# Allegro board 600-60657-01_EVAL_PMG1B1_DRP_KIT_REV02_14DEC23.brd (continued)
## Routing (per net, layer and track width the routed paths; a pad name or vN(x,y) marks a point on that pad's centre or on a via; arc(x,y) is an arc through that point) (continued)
C4: length 45.7
  TOP w0.381: v1(77.52,59.2) C89.2 C85.1 79.27,63.17 78.51,63.93 R86.1
  PWR/SIG w0.381: v1(77.52,59.2) 74.08,59.2 73.43,58.55 73.43,49.96 61.68,38.2 v1(61.68,31.2)
  BOTTOM w0.381: R79.1 v1(61.68,31.2)
CC1: length 91.9
  TOP w0.203: v3(75.97,47.36) 75.97,47.07 75.78,46.88 C22.1 75.29,46.45 75.44,46.3 76.27,46.3 76.66,45.91 77.46,45.91 78.01,45.36 U3.19 ; v2(104.31,4.91) 104.23,5 J10.A5
  PWR/SIG w0.305: v2(104.31,4.91) 104.88,4.91 105.18,5.22 105.18,5.92 104.88,6.22 104.47,6.22 103.7,6.99 98.48,6.99 74.85,30.62 74.85,42.28 76.97,44.4 76.97,46.36 v3(75.97,47.36)
  BOTTOM w0.305: D14.2 104.55,4.75 104.39,4.91 v2(104.31,4.91) ; v3(75.97,47.36) 75.49,47.36 74.92,46.79 55.16,46.79 54.78,47.17 J6.4
CC1_KP: length 2.2
  TOP w0.188: J1.A5 v1(7.35,38.49)
  BOTTOM w0.188: v1(7.35,38.49) 7.24,38.6 R70.2
CC2: length 92
  TOP w0.203: v2(104.59,6.84) 104.68,6.75 J10.B5 ; v3(77.43,47.33) 77.43,47.11 77.2,46.88 C25.1 76.74,46.44 76.89,46.29 77.7,46.29 78.41,45.58 U3.18
  PWR/SIG w0.305: v3(77.43,47.33) 77.43,44.21 75.31,42.09 75.31,30.82 98.67,7.45 103.98,7.45 v2(104.59,6.84)
  BOTTOM w0.305: v2(104.59,6.84) 104.61,6.82 104.62,6.82 104.69,6.75 J10.B5 ; v3(77.43,47.33) 77.43,46.67 77.08,46.31 52.62,46.31 52.24,46.7 J6.5
CC2_KP: length 2.2
  TOP w0.188: v1(7.3,35.49) J1.B5
  BOTTOM w0.188: R71.2 6.31,35.49 v1(7.3,35.49)
COMP: length 8
  TOP w0.188: U3.13 80.41,44.92 80.64,45.15 C38.1 84.21,46.02 84.3,46.11 84.3,46.97 R42.1
CSNO: length 37.1
  TOP w0.14: v5(79.42,48.3) 79.16,48.04 79.16,47.1 79.3,46.96 C27.2 79.81,46.47 79.16,45.82 79.16,43.34 79.21,43.28 U3.16 ; R49.1 98.21,61.96 97.73,61.48 97.73,60.88 v5(97.99,60.62)
  BOTTOM w0.14: v5(97.99,60.62) 97.74,60.37 97.74,58.59 95.91,56.76 81.14,56.76 80.54,56.15 80.54,50.48 79.17,49.12 79.17,48.54 v5(79.42,48.3)
CSPO: length 37.2
  TOP w0.14: R47.1 96.95,61.96 97.44,61.47 97.44,60.88 v5(97.18,60.62) ; U3.17 78.81,43.28 78.86,43.34 78.86,45.82 78.21,46.48 C27.1 78.72,46.96 78.86,47.1 78.86,48.04 v5(78.6,48.3)
  BOTTOM w0.14: v5(97.18,60.62) 97.45,60.35 97.45,58.71 95.79,57.05 81.02,57.05 80.25,56.28 80.25,50.61 78.88,49.24 78.88,48.57 v5(78.6,48.3)
DM_GPIO1: length 112.1
  TOP w0.14: v2(104.59,5.52) 104.82,5.75 J10.B7 ; v2(102.89,6.4) 103.14,6.16 103.46,6.16 103.58,6.29 J10.A7 ; U3.21 77.21,43.28 77.26,43.34 77.26,44.97 76.97,45.27 76.18,45.27 v2(75.93,45.03)
  PWR/SIG w0.114: v2(104.59,5.52) 103.78,5.52 v2(102.89,6.4) 102.65,6.16 97.92,6.16 74.17,29.91 74.17,44.25 75.19,45.27 75.69,45.27 v2(75.93,45.03)
  BOTTOM w0.14: J6.12 35.44,48.17 35.58,48.03 35.58,45.97 36.28,45.27 75.69,45.27 v2(75.93,45.03) ; DM_GPIO1.1 106.64,6.8 106.13,6.29 104.18,6.29 103.98,6.5 J10.A7 102.99,6.5 v2(102.89,6.4)
DP_GPIO0: length 112.6
  TOP w0.14: v2(75.93,45.81) 76.18,45.56 77.09,45.56 77.56,45.09 77.56,43.34 77.61,43.28 U3.20 ; v2(102.89,5.62) 103.14,5.87 103.44,5.87 103.58,5.73 J10.A6 103.97,5.5 104.72,6.25 J10.B6
  PWR/SIG w0.114: v2(102.89,5.62) 102.65,5.87 97.8,5.87 73.88,29.78 73.88,44.37 75.07,45.56 75.69,45.56 v2(75.93,45.81)
  BOTTOM w0.14: J6.11 36.01,48.17 35.87,48.03 35.87,46.09 36.4,45.56 75.69,45.56 v2(75.93,45.81) ; v2(102.89,5.62) 103.02,5.5 J10.A6 103.58,5.87 103.71,6 106.15,6 106.66,5.49 DP_GPIO0.1
HG1: length 15.8
  TOP w0.203: U3.2 81.88,37.97 v3(82.44,37.41)
  TOP w0.254: v2(93.33,36.94) 93.31,36.91 93.31,36.5 93.41,36.4 Q8.4 93.8,36.4 94.05,36.65 v2(94.05,36.94)
  TOP w0.406: v3(82.44,37.41) v3(82.86,36.99)
  PWR/SIG w0.406: v3(82.44,37.41) v3(82.86,36.99) 83.27,36.57 89.31,36.57 89.67,36.94 v2(93.33,36.94) 94.05,36.94 v2(94.05,36.94)
HG2: length 18.6
  TOP w0.203: U3.10 82.05,41.17 v3(82.55,41.67)
  TOP w0.254: v2(94.03,45.28) 94.03,44.85 93.84,44.66 Q7.4 93.56,44.66 93.38,44.84 v2(93.38,45.29)
  TOP w0.406: v3(82.55,41.67) 82.95,42.07 v3(83,42.07)
  PWR/SIG w0.406: v2(94.03,45.28) 94.03,45.29 v2(93.38,45.29) 93.02,45.65 84.1,45.65 83,44.55 v3(83,42.07) 82.61,41.67 v3(82.55,41.67)
I2C0_SCL: length 45.1
  TOP w0.188: U3.42 78.01,33.51 75.56,31.06 75.56,30.17 75.42,30.03 R35.1 R31.2 73.44,29.45 v2(73.19,29.19)
  BOTTOM w0.188: v2(73.19,29.19) 73.19,30.5 73.04,30.65 71.84,30.65 70.52,31.98 48.61,31.98 47.67,31.04 47.67,27.34 J7.6
I2C0_SDA: length 43.4
  TOP w0.188: U3.41 77.61,33.67 75.42,31.47 R34.1 73.49,31.47 R30.2 73.44,32.12 v2(73.19,32.37)
  BOTTOM w0.188: v2(73.19,32.37) 73.19,31.19 73.01,31.01 72.07,31.01 70.72,32.36 48.22,32.36 47.16,31.3 J7.7
I2C_SCL: length 90.1
  TOP w0.188: R31.1 70.68,30.03 70.47,30.24 v2(70.47,31.07) ; U1.38 14.13,32.05 14.05,31.96 R4.1 14.6,30.58 14.76,30.42 14.76,28.94 v5(15.2,28.5)
  PWR/SIG w0.15: v2(70.47,31.07) 69.12,31.07 68.22,30.17 55.14,30.17 54.93,30.38 54.93,42.15 54.33,42.76 43.29,42.76 38.8,38.27 35.65,38.27 J4.4 33.8,40.12 v1(33.03,40.12) 33.03,39.53 32.88,39.38 31.29,39.38 31.09,39.57 v1(31.09,40.14) 30.68,40.55 28.11,40.55 J3.4
  BOTTOM w0.188: v5(15.2,28.5) 15.36,28.34 23.81,28.34 24.78,29.32 24.78,38.93 25.22,39.37 J3.4
I2C_SDA: length 88.1
  TOP w0.188: U1.39 14.53,31.43 v5(14.63,31.33) ; v2(70.94,30.54) 70.94,31.31 71.15,31.52 R30.1
  PWR/SIG w0.15: J3.6 28.12,38.03 30.77,38.03 v1(31.1,37.7) 31.1,37.15 31.25,37 32.8,37 32.96,37.15 v1(32.96,37.71) 33.66,37.71 J4.6 35.66,37.94 38.97,37.94 43.47,42.45 54.08,42.45 54.62,41.91 54.62,30.21 54.97,29.86 68.41,29.86 69.09,30.54 v2(70.94,30.54)
  BOTTOM w0.188: R63.1 14.05,31.13 14.26,31.33 v5(14.63,31.33) 14.63,28.32 14.95,28 24.07,28 25.27,29.19 25.27,35.17 J3.6
IIN_CSN: length 13.5
  TOP w0.14: SP1.2 88.42,29.51 88.37,29.47 87.45,29.47 86.98,29.94 86.98,32.79 85.36,34.4 81.95,34.4 80.36,36 80.36,36.2 80.41,36.25 U3.48
IIN_CSP: length 14
  TOP w0.14: U3.47 80.01,36.25 80.06,36.2 80.06,35.88 81.83,34.11 85.24,34.11 86.69,32.67 86.69,29.82 87.33,29.18 88.38,29.18 88.42,29.13 SP2.2
IOUT_CSN: length 1.1
  TOP w0.14: SP4.1 97.77,63.83 98.2,63.41 R49.2
IOUT_CSP: length 1
  TOP w0.14: R47.2 96.95,63.41 97.39,63.85 SP3.1
KP3_UART_RX: length 61.8
  TOP w0.188: v5(24.4,42.29) 23.82,41.71 23.82,40.86 26.05,38.63 26.05,38.62 26.07,38.61 26.07,37.71 25.73,37.38 25.73,35.48 J3.8 ; v1(53.19,41.22) 54.87,39.55 R26.1 ; U1.21 11.32,38.72 v5(11.1,38.94)
  PWR/SIG w0.15: v1(53.19,41.22) 52.96,40.99 44.05,40.99 44.04,40.97 43.91,40.97 38.39,35.45 36.66,35.45 35.5,34.29 J4.8 33.88,34.96 v1(32.98,34.96) 32.98,34.51 32.82,34.35 31.31,34.35 31.07,34.6 v1(31.07,35.03) 30.66,35.44 28.08,35.44 J3.8
  BOTTOM w0.188: v5(11.1,38.94) 11.41,39.25 11.41,39.95 13.86,42.4 14.4,42.4 15.79,43.79 22.9,43.79 v5(24.4,42.29)
KP3_UART_TX: length 69.4
  TOP w0.188: v1(53.22,40.43) 51.84,41.81 R25.1 ; J3.10 25.38,33.3 25.38,37.58 25.73,37.93 25.73,38.47 23.37,40.83 23.37,42.15 24.18,42.96 v5(24.6,42.96) ; U1.20 11.63,39.12 v5(10.88,39.87)
  PWR/SIG w0.15: v1(53.22,40.43) 52.96,40.69 44.18,40.69 38.63,35.14 38.63,33.98 37.72,33.07 36.83,33.07 35.51,31.75 J4.10 33.91,32.39 v1(33.04,32.39) 33.04,31.68 32.89,31.53 31.25,31.53 31.07,31.71 v1(31.07,32.39) 30.59,32.87 28.05,32.87 J3.10
  BOTTOM w0.188: v5(24.6,42.96) 24.21,42.96 23.03,44.14 15.62,44.14 14.22,42.74 14.2,42.74 13.72,42.74 11.01,40.03 11.01,40 v5(10.88,39.87)
KP_CLK: length 26
  TOP w0.188: v5(15.65,42.39) 15.34,42.08 15.34,41.91 14.93,41.5 U1.12
  BOTTOM w0.188: J2.4 15.06,26.82 11.93,26.82 10.49,28.26 10.49,31.2 12.25,32.95 12.25,39.72 13.57,41.04 14.38,41.04 15.65,42.31 v5(15.65,42.39)
KP_DM: length 10.8
  TOP w0.14: v1(8.63,38.94) 8.63,38.94 8.78,38.79 arc(8.87,38.65) 8.91,38.49 8.91,38.45 arc(8.95,38.24) 9.06,38.07 9.22,37.91 arc(9.3,37.8) 9.32,37.66 9.32,37.52 arc(9.28,37.43) 9.2,37.39 9.06,37.39 arc(9.01,37.4) 8.97,37.43 8.82,37.58 arc(8.78,37.6) 8.73,37.61 D1.2 8.6,37.61 8.46,37.61 arc(8.41,37.6) 8.37,37.57 8.22,37.42 arc(8.18,37.4) 8.13,37.39 8.13,37.38 arc(8.12,37.38) 8.12,37.38 7.01,37.38 7.01,37.39 arc(6.94,37.4) 6.88,37.44 arc(6.82,37.48) 6.75,37.49 J1.B7 5.52,37.49 arc(5.45,37.48) 5.4,37.44 arc(5.34,37.4) 5.27,37.39 4.87,37.39 arc(4.5,37.23) 4.34,36.86 4.34,36.64 arc(4.5,36.25) 4.89,36.09 5.34,36.09 arc(5.4,36.08) 5.45,36.04 arc(5.51,36.01) 5.58,35.99 J1.A7
  BOTTOM w0.14: v1(8.63,38.94) 8.9,39.21 arc(8.93,39.25) 8.94,39.31 8.94,39.34 arc(8.93,39.4) 8.9,39.44 8.55,39.79 arc(8.49,39.8) R68.1
KP_DP: length 10.3
  TOP w0.14: J1.B6 5.56,36.49 arc(5.5,36.48) 5.44,36.44 arc(5.39,36.41) 5.33,36.39 4.88,36.39 arc(4.72,36.46) 4.65,36.62 4.65,36.83 arc(4.73,37.02) 4.92,37.1 5.34,37.1 arc(5.38,37.09) 5.43,37.06 5.44,37.05 arc(5.5,37.01) 5.56,36.99 6.15,36.99 J1.A6 6.15,36.99 6.76,36.99 arc(6.82,37.01) 6.88,37.04 arc(6.93,37.08) 6.99,37.09 8.12,37.09 arc(8.16,37.08) 8.21,37.05 8.34,36.92 arc(8.4,36.88) 8.47,36.87 D2.2 arc(8.77,36.9) 8.92,37 8.98,37.06 arc(9.02,37.09) 9.08,37.1 9.2,37.1 arc(9.5,37.22) 9.62,37.52 9.61,37.53 9.61,37.66 arc(9.57,37.91) 9.43,38.12 9.31,38.24 arc(9.26,38.32) 9.24,38.41 9.24,38.45 arc(9.27,38.62) 9.37,38.77 9.54,38.94 v1(9.55,38.94)
  BOTTOM w0.14: v1(9.55,38.94) 9.28,39.21 arc(9.25,39.26) 9.24,39.31 9.24,39.35 arc(9.25,39.41) 9.28,39.45 9.59,39.77 arc(9.64,39.8) R67.1
KP_IO: length 29.4
  TOP w0.188: U1.11 15.33,41.35 v5(16.73,42.76)
  BOTTOM w0.188: J2.5 18.34,26.08 17.43,26.08 16.27,27.24 12.05,27.24 10.9,28.39 10.9,31.08 12.65,32.83 12.65,39.59 12.66,39.6 12.66,39.61 13.73,40.68 13.74,40.68 13.75,40.69 14.67,40.69 v5(16.73,42.76)
KP_VBUS_IN: length 17.6
  TOP w0.45: v1(7.5,39.34) 7.13,39.34 6.88,39.09 J1.A4 ; J1.B4 v1(7.5,34.39)
  TOP w0.635: v4(9.84,46.43) 9.36,46.91 8.16,46.91 7.35,46.09 7.35,41.58 7.94,40.98 7.94,39.78 v1(7.5,39.34)
  BOTTOM w0.7: v4(20.67,48.72) 21.1,48.29 R62.1
  vias: v1(9.44,48.03) v4(11.15,46.49)
KP_VBUS_P: length 55
  TOP w0.508: R4.2 v1(14.05,28.44) ; D4.A 35.26,44.5 34.55,43.78 J4.2
  PWR/SIG w0.635: v4(22.9,44.79) 25.03,44.79 26.93,42.9 J3.2 24.4,39.38 24.4,31.27 19.88,26.75 15.74,26.75 v1(14.05,28.44)
  BOTTOM w0.508: R61.1 v1(28.55,45.89) ; R4.2 v1(14.05,28.44)
  BOTTOM w0.635: J3.2 28.91,43.89 30.61,43.89 v1(31.08,43.42) 31.08,42.34 31.32,42.11 32.65,42.11 32.98,42.44 v1(32.98,43.41) 34.09,43.41 34.55,42.96 J4.2
  BOTTOM w0.7: R62.2 26.52,47.87 v4(27.3,47.09)
  vias: v1(24.2,46.99) v1(25.2,47.29) v1(26.1,46.79) v4(22.9,46.14)
LG1: length 23.6
  TOP w0.203: v3(82.75,38.68) 82.67,38.77 U3.4
  TOP w0.254: v2(98.95,36.4) Q11.4 98.1,36.69 98.35,36.95 v2(98.95,36.95)
  TOP w0.406: v3(82.75,38.68) v3(83.16,38.27)
  PWR/SIG w0.406: v3(82.75,38.68) v3(83.16,38.27) 83.7,38.27 85,39.57 97.64,39.57 98.95,38.26 v2(98.95,36.95) v2(98.95,36.4)
LG2: length 24.6
  TOP w0.203: v3(82.92,40.05) 82.83,39.97 U3.7
  TOP w0.254: v2(98.95,44.66) Q10.4 98.1,44.94 98.35,45.19 v2(98.95,45.19)
  TOP w0.406: v3(83.31,40.48) 83.25,40.43 83.25,40.42 82.92,40.09 82.92,40.06 v3(82.92,40.05)
  PWR/SIG w0.406: v3(82.92,40.05) 82.92,40.09 v3(83.31,40.48) 97.66,40.48 98.96,41.78 98.96,44.14 98.95,44.15 v2(98.95,44.66) v2(98.95,45.19)
LOAD_SWITCH_EN_H: length 61.3
  TOP w0.188: R44.1 v1(86.88,11.43) ; v3(72.78,40.93) 72.95,40.77 U3.28
  PWR/SIG w0.15: v3(72.78,40.93) 72.78,38.97 71.87,38.06 71.87,29.21 v2(72.86,28.22) 80.26,20.82 80.26,20.82 86.33,14.75 86.33,14.75 86.88,14.21 v1(86.88,11.43)
  BOTTOM w0.188: v2(72.86,28.22) 72.86,24.91 72.31,24.36 55.73,24.36 J7.4
NTCP0: length 60.4
  TOP w0.188: R46.2 C52.2 NTC0.2 ; NTC0.2 93.55,1.49 93.7,1.33 NTCP0.1 ; NTC0.2 93.53,2.58 v2(92.74,2.58) ; v3(73.1,44.12) 76.07,44.12 76.41,43.78 U3.23
  PWR/SIG w0.15: v3(73.1,44.12) 73.3,43.92 73.3,42.78 73.31,42.77 73.31,42.4 73.3,42.39 73.3,38.95 72.2,37.85 72.2,29.54 74.69,27.06 75.62,27.06 92.74,9.93 v2(92.74,2.58)
NTCP1: length 48.3
  TOP w0.188: NTCP1.1 C59.2 NTC1.2 ; v3(103.86,50.41) NTC1.2 ; NTC1.2 104.66,50.81 105.05,51.19 R51.2 ; v3(72.59,43.64) 75.86,43.64 76.01,43.48 U3.24
  PWR/SIG w0.15: v3(103.86,50.41) 103.34,49.89 87.19,49.89 84.36,52.72 76.85,52.72 76.16,52.03 76.16,48.29 72.59,44.72 v3(72.59,43.64)
P1_3/AIN4: length 27.5
  TOP w0.188: U3.34 64.07,38.37 63.55,37.84 SW7.2 63.55,27.99 62.96,27.4 60.27,27.4 59.86,26.99 J7.2
P1_4/AIN3: length 35.5
  TOP w0.188: J7.5 52.24,30 52.72,30.49 SW6.2 61.91,30.49 62.48,31.06 62.48,38.3 62.96,38.77 U3.33
P1_7/BAT_TH_SNS: length 37.8
  TOP w0.188: U3.30 64.07,39.97 63.55,40.49 SW8.2 63.55,43.58 62.67,44.45 62.67,45.75 62.5,45.92 44.82,45.92 44.62,46.13 J6.8
P5LP1_2: length 32.1
  TOP w0.203: v5(23.73,28.99) SW1.1 SW1.2 ; U1.13 14.53,41.86 v5(14.57,41.9)
  BOTTOM w0.254: v5(23.73,28.99) 24.41,29.67 24.41,39.22 25.02,39.83 25.02,41.37 24.7,41.69 24.19,41.69 22.59,43.29 15.82,43.29 14.9,42.37 14.9,42.23 v5(14.57,41.9)
P5LP1_4: length 14.8
  TOP w0.188: v5(13.92,41.61) 13.73,41.42 U1.15
  BOTTOM w0.188: v5(13.92,41.61) 13.6,41.61 11.91,39.91 11.91,33.09 9.9,31.09 R66.1
P5LP_SIO_VREF: length 3.6
  TOP w0.203: R7.2 18.04,30.64 18.13,30.73 U1.48
  TOP w0.381: R8.2 R7.2
P5LP_VCCD: length 30.2
  TOP w0.203: U1.26 11.65,36.72 11.4,36.46 11.4,35.39 11.18,35.17 ; U1.57 21.1,35.52
  TOP w0.254: v5(10.97,35.84) 10.76,35.84 10.46,35.54 C77.1 11.18,35.17 ; 21.1,35.52 21.37,35.52 21.57,35.32 C67.1 22.13,35.78 21.9,36.01 v5(21.55,36.01)
  PWR/SIG w0.635: v5(21.55,36.01) 22.23,35.32 22.23,32.68 19.47,29.92 11.7,29.92 10.98,30.64 10.98,35.77 10.97,35.78 v5(10.97,35.84)
  BOTTOM w0.381: C77.1 10.46,35.28 10.95,35.77 10.95,35.82 v5(10.97,35.84)
  BOTTOM w0.508: C9.1 v5(21.55,36.01)
P5LP_VDD: length 36
  TOP w0.203: 16.53,31.93 U1.44 ; 21,39.52 U1.67 ; U1.24 11.48,37.52 11.16,37.21 ; U1.17 12.93,41.57 13.02,41.67 ; 20.87,33.52 U1.52 ; 12.93,31.99 U1.35 ; 20.91,36.32 U1.59
  TOP w0.254: C2.1 10.91,36.57 11.16,36.82 11.16,37.21 ; C8.1 21.31,36.72 20.91,36.32
  TOP w0.381: v5(22.13,40.32) C7.1 22.12,39.52 21,39.52 ; 20.87,33.52 21.27,33.92 C10.1 22.13,33.51 21.75,33.13 v5(21.45,33.13) ; C2.1 10.59,36.57 v5(10.59,37.44) ; C6.1 16.64,31.83 16.53,31.93 ; C4.1 13.68,42.32 13.02,41.67 ; 12.93,31.99 12.93,31.67 12.52,31.26 C3.1
  TOP w0.457: C4.1 13.68,42.87 v5(14.25,43.44)
  TOP w0.508: v5(11.84,30.8) 12.12,30.52 C3.1 ; R2.1 v5(8.83,42.84) ; v5(21.58,37.27) 21.86,37.27 22.13,37.01 C8.1 ; C6.1 16.61,30.59 16.1,31.1 v5(16.1,31.19)
  PWR/SIG w0.508: J2.1 8.92,26.34 ; J2.1 9.92,25.34 ; J2.1 7.92,25.34
  BOTTOM w0.457: v5(14.25,43.44) 14.02,43.21 C71.1 12.47,43.21
  BOTTOM w0.508: v5(11.84,30.8) 12.12,30.52 C3.1 ; v5(16.1,31.19) 16.13,31.19 16.64,30.68 C6.1 ; 12.47,43.21 12.15,42.89 R64.1 9.46,42.89 9.41,42.84 v5(8.83,42.84) ; C66.1 v5(21.58,37.27) ; C73.1 10.08,36.94 10.58,37.44 v5(10.59,37.44) ; C68.1 v5(21.45,33.13) ; C7.1 v5(22.13,40.32)
  vias: v1(8.4,33.19) v1(8.67,29.79) v1(18.08,41.73) v5(21.04,40.89) v5(21.21,38.73) v5(23,38.76)
RESET: length 87.1
  TOP w0.188: U1.3 18.53,41.45 18.97,41.89 21.69,41.89 24.96,38.63 24.96,38.42 v5(25.25,38.12) ; v2(64.07,27.01) R19.2 65.32,27.01 65.33,27 C13.2 SW3.1 SW3.2 65.96,33.15 66.14,33.34 73.24,33.34 73.68,33.78 76.75,33.78 77.21,34.25 U3.40 ; J8.10 v1(44.76,38.78) 39.03,38.78 J4.5
  PWR/SIG w0.15: v2(64.07,27.01) 63.81,27.28 45.29,27.28 44.76,27.81 v1(44.76,38.78) ; J3.5 30.31,35.98 v1(31.08,35.98) 31.08,36.49 31.23,36.64 32.79,36.64 32.98,36.45 v1(32.98,35.95) 33.45,35.48 35.74,35.48 J4.5
  BOTTOM w0.188: v5(25.25,38.12) 28.17,38.12 J3.5
SOURCE_BUCK_EN_H: length 67.4
  TOP w0.188: 64.95,24.36 64.72,24.13 35.64,24.13 J7.12 ; 64.95,24.36 65.17,24.14 68.27,24.14 68.61,23.79 68.61,15.65 69.18,15.08 R22.1 ; 64.95,24.36 v2(64.95,24.96) ; U3.39 76.81,34.53 76.57,34.3 C21.1 73.57,34.3 72.95,33.68 65.64,33.68 65.29,33.33 65.29,28.51 v2(64.95,28.17)
  PWR/SIG w0.15: v2(64.95,28.17) v2(64.95,24.96)
SOURCE_FAULT_FLAG: length 65.5
  TOP w0.188: U3.38 76.41,34.97 76.18,34.74 74.13,34.74 74.07,34.79 71.59,34.79 v2(71.4,34.6)
  PWR/SIG w0.15: J7.11 37.92,24.39 v1(75.64,24.39) 75.64,24.79 71.4,29.04 v2(71.4,34.6)
  BOTTOM w0.188: R54.1 76.49,19.27 76.77,19.55 76.77,23.26 v1(75.64,24.39)
SOURCE_OUTPUT_V_SELECT: length 58.1
  TOP w0.188: v3(72.25,40.45) 72.67,40.45 72.75,40.37 U3.29
  PWR/SIG w0.15: v2(70.9,32.81) 70.9,34.82 71.47,35.39 71.47,38.1 72.25,38.89 v3(72.25,40.45)
  BOTTOM w0.188: Q14.1 R55.1 73.82,32.66 73.48,33.01 71.1,33.01 v2(70.9,32.81) 70.88,32.8 47.99,32.8 46.7,31.51 46.7,27.4 J7.8
SW_1: length 20.3
  TOP w0.203: C36.1 83.29,37.37 82.29,38.37 U3.3
  TOP w0.381: v3(85.28,37.76) v3(84.7,37.76) 84.31,37.37 C36.1
  PWR/SIG w0.406: v3(84.7,37.76) v3(85.28,37.76) 87.34,37.76 87.59,38.01 96.52,38.01 96.93,37.6 v2(96.93,36.38) v2(96.93,35.74) v2(96.93,35.11) v2(96.93,34.47)
  vias: v2(93.38,35.74) v2(93.38,35.11) v2(93.38,34.47) v2(93.99,35.74) v2(93.99,35.11) v2(93.99,34.47) v2(95.02,36.38) v2(95.02,35.74) v2(95.02,35.11) v2(95.02,34.47) v2(95.66,36.38) v2(95.66,35.74) v2(95.66,35.11) v2(95.66,34.47) v2(96.29,36.38) v2(96.29,35.74) v2(96.29,35.11) v2(96.29,34.47) v4(101.98,36.61) v4(101.98,35.46) v4(101.98,34.32) v4(103.12,36.61) v4(103.12,35.46) v4(103.12,34.32) v4(104.26,36.61) v4(104.26,35.46) v4(104.26,34.32) v4(105.41,36.61) v4(105.41,35.46) v4(105.41,34.32) v4(106.55,36.61) v4(106.55,35.46) v4(106.55,34.32) v4(107.69,36.61) v4(107.69,35.46) v4(107.69,34.32)
SW_2: length 19.8
  TOP w0.203: C35.2 83.14,41.57 82.33,40.77 U3.9
  TOP w0.381: v3(85.36,42.17) v3(84.78,42.17) 84.36,42.17 C35.2
  PWR/SIG w0.406: v2(96.93,44.64) v2(96.93,44) v2(96.93,43.37) v2(96.93,42.73) 96.93,42.08 96.52,41.67 87.55,41.67 87.06,42.17 v3(85.36,42.17) v3(84.78,42.17)
  vias: v2(93.38,44) v2(93.38,43.37) v2(93.38,42.73) v2(93.99,44) v2(93.99,43.37) v2(93.99,42.73) v2(95.02,44.64) v2(95.02,44) v2(95.02,43.37) v2(95.02,42.73) v2(95.66,44.64) v2(95.66,44) v2(95.66,43.37) v2(95.66,42.73) v2(96.29,44.64) v2(96.29,44) v2(96.29,43.37) v2(96.29,42.73) v4(101.98,45.55) v4(101.98,44.4) v4(101.98,43.26) v4(103.12,45.55) v4(103.12,44.4) v4(103.12,43.26) v4(104.26,45.55) v4(104.26,44.4) v4(104.26,43.26) v4(105.41,45.55) v4(105.41,44.4) v4(105.41,43.26) v4(106.55,45.55) v4(106.55,44.4) v4(106.55,43.26) v4(107.69,45.55) v4(107.69,44.4) v4(107.69,43.26)
SWD_CLK: length 57.8
  TOP w0.188: U3.36 73.43,37.57 73.1,37.24 v3(73.1,36.27) ; J8.4 44.33,34.97 44.22,35.08 R10.2 R12.1 v1(41.8,36.48)
  PWR/SIG w0.15: J7.9 41.34,25.31 41.12,25.53 41.12,30.51 42.63,32.01 42.63,35.65 v1(41.8,36.48)
  BOTTOM w0.188: v1(41.8,36.48) 41.8,34.87 42.06,34.6 43.14,34.6 46.92,38.39 70.11,38.39 72.23,36.27 v3(73.1,36.27)
SWD_DAT: length 54.6
  TOP w0.188: J8.2 44.44,33.7 44.33,33.58 R11.2 R13.1 v1(41.8,32.19) ; U3.37 76.01,35.36 v3(75.9,35.25)
  PWR/SIG w0.15: v1(41.8,32.19) 40.6,30.99 40.6,25.57 40.34,25.31 J7.10
  BOTTOM w0.188: v3(75.9,35.25) 72.58,35.25 69.78,38.05 47.24,38.05 43.21,34.02 42.07,34.02 41.8,33.75 v1(41.8,32.19)
SWDCLK: length 35.8
  TOP w0.188: J4.7 37.88,35.08 R10.1 ; U1.47 17.73,31.26 17.56,31.08 17.56,28.42 v5(18.5,27.48)
  PWR/SIG w0.15: J4.7 35.9,33.1 v1(33.03,33.1) 33.03,33.82 32.84,34.01 31.29,34.01 31.08,33.8 v1(31.08,33.18) 30.58,33.18 J3.7
  BOTTOM w0.188: v5(18.5,27.48) 24.19,27.48 25.69,28.98 25.69,32.27 26.6,33.18 28.36,33.18 J3.7
SWDIO: length 37.1
  TOP w0.188: U1.46 17.33,31.39 17.21,31.27 17.21,27.98 v5(17.7,27.49) ; R11.1 38.92,33.58 J4.9
  PWR/SIG w0.15: J3.9 29.47,30.51 29.77,30.2 v1(31.02,30.2) 31.02,30.94 31.25,31.18 32.87,31.18 33.03,31.01 v1(33.03,30.19) 35.53,30.19 J4.9
  BOTTOM w0.188: J3.9 29.47,29.13 27.34,27 18.19,27 v5(17.7,27.49)
TH: length 43.4
  PWR/SIG w0.381: J13.1 83.47,69.93 83.08,69.54 71.5,69.54 71.03,69.07 71.03,50.36 v1(64.95,44.29)
  BOTTOM w0.381: R83.1 65.35,43.89 v1(64.95,44.29)
UART2_RX: length 1.9
  TOP w0.188: R25.2 SW4.1
UART2_RX/AIN1: length 41
  TOP w0.188: U3.31 57.98,39.57 57.49,40.06 SW4.2 57.49,45.23 57.16,45.56 42.56,45.56 42.08,46.04 J6.9
UART2_TX: length 1.9
  TOP w0.188: R26.2 SW5.1
UART2_TX/AIN2: length 46.6
  TOP w0.188: J6.10 39.54,45.96 40.28,45.21 50.04,45.21 50.23,45.02 50.23,42.35 53.62,38.97 53.62,36.97 53.85,36.74 SW5.2 60.52,38.65 61.03,39.17 U3.32
UART_CTS: length 2.3
  TOP w0.188: U1.61 20.67,37.12 21.56,38.01 R9.2
USB_V_SENSE: length 7
  TOP w0.188: R1.2 R2.2 9.91,42.84 10.16,42.59 10.16,40.86 10.68,40.35 11.21,40.35 11.44,40.12 11.44,39.81 11.73,39.52 U1.19
USER_STATUS_LED: length 36
  TOP w0.188: R21.1 69.63,40.57 ; 69.63,40.57 69.44,40.38 65.04,40.38 64.59,40.83 64.59,43.77 64.3,44.06 63.6,44.06 63.08,44.58 63.08,45.94 62.76,46.26 47.54,46.26 47.16,46.65 J6.7 ; 69.63,40.57 69.82,40.38 71.52,40.38 72.54,41.41 72.98,41.41 73.22,41.17 U3.27
USER_SWITCH: length 22.2
  TOP w0.188: U3.26 73.3,41.57 72.76,42.11 72.65,42.11 71.83,42.93 71.83,45.64 70.64,46.83 R17.1 68.51,47.45 68.38,47.58 66.7,47.58 66.49,47.79 66.49,48.96 66.13,49.32 60.18,49.32 59.86,48.99 J6.2
VOUT: length 25.3
  TOP w0.203: v3(84.76,41.42) 84.31,40.97 83.11,40.97 83.11,40.96 83.03,40.96 82.44,40.37 U3.8
  TOP w0.381: v3(85.35,41.42) v3(84.76,41.42)
  TOP w0.508: C51.1 83.26,57.03 81.21,54.98 R39.1
  PWR/SIG w0.406: v2(92.51,42.73) v2(91.88,42.73) v2(91.24,42.73) v2(90.61,42.73) 88.13,42.73 87.7,43.16 84.44,43.16 84.03,42.76 84.03,41.83 84.44,41.42 v3(84.76,41.42) v3(85.35,41.42)
  vias: v2(90.61,44.64) v2(90.61,44) v2(90.61,43.37) v2(91.24,44.64) v2(91.24,44) v2(91.24,43.37) v2(91.88,44.64) v2(91.88,44) v2(91.88,43.37) v2(92.48,44.6) v2(92.51,44) v2(92.51,43.37) v4(80.97,67.77) v4(80.97,66.5) v4(80.97,65.23) v4(80.97,63.96) v4(82.24,67.77) v4(82.24,66.5) v4(82.24,65.23) v4(82.24,63.96) v4(83.51,67.77) v4(83.51,66.5) v4(83.51,65.23) v4(83.51,63.96) v4(84.78,67.77) v4(84.78,66.5) v4(84.78,65.23) v4(84.78,63.96)
VOUT_BUCK:
  vias: v2(82.05,15.36) v2(82.05,14.59) v2(82.05,13.83) v2(82.05,13.07) v2(82.05,12.31) v2(82.05,11.55) v2(82.05,10.78) v2(82.71,15.36) v2(82.71,14.59) v2(82.71,13.83) v2(82.71,13.07) v2(82.71,12.31) v2(82.71,11.55) v2(82.71,10.78) v2(83.48,15.36) v2(83.48,14.59) v2(83.48,13.83) v2(83.48,13.07) v2(83.48,12.31) v2(83.48,11.55) v2(83.48,10.78) v2(84.14,15.36) v2(84.14,14.59) v2(84.14,13.83) v2(84.14,13.07) v2(84.14,12.31) v2(84.14,11.55) v2(84.14,10.78) v2(84.11,6.92) v2(84.11,6.36) v2(84.11,5.81) v2(84.11,5.25) v2(84.11,4.69) v2(84.11,4.13)
VOUT_DC: length 64.2
  TOP w0.14: R90.2 v1(75.79,56.73) ; SP4.2 97.77,66.39 97.93,66.55 R48.2
  TOP w0.508: 107.26,63.41 J9.2 ; J9.2 106.2,64.46 ; J9.2 107.26,65.52 ; J9.2 108.31,64.46 ; 101.22,66.52 TP10.1 ; TP10.1 100.31,67.43 ; TP10.1 102.13,67.43 ; TP10.1 101.22,68.35
  GND w0.508: J9.2 107.26,65.52 ; J9.2 106.2,64.46 ; J9.2 107.26,63.41 ; J9.2 108.31,64.46 ; 100.31,67.43 TP10.1 ; TP10.1 101.22,66.52 ; TP10.1 102.13,67.43 ; TP10.1 101.22,68.35
  PWR/SIG w0.508: 106.2,64.46 J9.2 ; J9.2 108.31,64.46 ; J9.2 107.26,63.41 ; J9.2 107.26,65.52 ; 101.22,66.52 TP10.1 ; TP10.1 101.22,68.35 ; TP10.1 102.13,67.43 ; TP10.1 100.31,67.43
  BOTTOM w0.14: v1(75.79,56.73) 75.79,57.59 76.61,58.41 95.53,58.41 96.18,59.06 96.18,62.3 96.52,62.63 99.95,62.63
  BOTTOM w0.508: J9.2 108.31,64.46 ; J9.2 107.26,63.41 ; J9.2 106.2,64.46 ; J9.2 107.26,65.52 ; 100.31,67.43 TP10.1 ; TP10.1 101.22,68.35 ; TP10.1 101.22,66.52 ; TP10.1 102.13,67.43
VOUT_DC_MEAS: length 6.4
  TOP w0.188: R81.2 R82.1 C83.1 72.47,37.76 72.68,37.97 U3.35
VOUT_U2: length 3.1
  BOTTOM w0.254: R53.2 v2(88.7,2.25)
VS_IN: length 62.9
  TOP w0.305: v2(72.09,11.84) v2(72.09,12.4) v2(72.09,12.96) v2(72.09,13.49) 72.11,13.52
  TOP w0.381: v1(74.93,23.68) 83.31,23.68 83.69,24.06 83.69,25.27 D17.A v1(83.68,26.23) ; v1(74.39,49.02) 73.77,49.64 D18.A
  PWR/SIG w0.381: v2(71.55,12.96) v2(71.55,13.49) 71.55,13.5 71.55,23.23 71.99,23.68 v1(74.93,23.68)
  BOTTOM w0.381: v1(83.68,26.23) 84.39,26.94 84.39,29.31 75.35,38.35 75.35,41.99 78.11,44.76 78.11,47.65 77.6,48.16 75.25,48.16 v1(74.39,49.02)
  BOTTOM w0.508: 70.89,3.62 J11.2 ; J11.2 71.94,4.67 ; J11.2 69.84,4.67 ; J11.2 70.89,5.72
  vias: v2(69.8,10.52) v2(69.8,9.99) v2(69.8,9.43) v2(69.8,8.87) v2(70.36,10.52) v2(70.36,9.99) v2(70.36,9.43) v2(70.36,8.87) v2(70.99,11.84) v2(70.99,11.28) v2(71.55,12.4) v2(71.55,11.84) v2(71.55,11.28) v2(72.09,11.28)
VTARG: length 20.2
  TOP w0.188: C11.2 TVS1.K 48.89,31.09 48.66,31.32 48.66,33.52 48.84,33.7 J8.1 52.86,33.7 53.19,34.03 53.19,38.83 50.12,41.9 D6.A
VTARG_MEAS: length 4.6
  TOP w0.203: 11.31,33.8 11.31,34.02 11.61,34.32 U1.32
  TOP w0.381: 11.31,33.8 11.31,33.1 11.1,32.88 R3.2 10.52,32.4 v5(10.22,32.09)
  BOTTOM w0.381: v5(10.22,32.09) 10.52,32.4 R3.2
XRES: length 39.6
  TOP w0.188: v5(17.5,42.44) 17.2,42.14 16.62,42.14 15.73,41.25 U1.10
  BOTTOM w0.188: J2.3 15.25,24.09 20.22,24.09 20.68,24.55 20.68,26.16 20.25,26.59 17.57,26.59 16.51,27.64 12.16,27.64 11.26,28.54 11.26,30.96 12.99,32.69 12.99,39.46 13.87,40.34 14.89,40.34 16.7,42.15 17.21,42.15 v5(17.5,42.44)
N01675: length 6.2
  TOP w0.254: v2(72.64,12.14) 72.64,12.84 v2(72.64,12.85) v2(72.64,13.46)
  GND w0.254: v2(72.64,13.46) v2(72.64,12.85) 72.64,12.84 v2(72.64,12.14)
  PWR/SIG w0.254: v2(72.64,13.46) v2(72.64,12.85) 72.64,12.84 v2(72.64,12.14)
  BOTTOM w0.254: C61.1 U5.7 72.9,14.01
  vias: v2(77.96,15.36) v2(77.96,14.59) v2(77.96,13.83) v2(77.96,13.07) v2(77.96,12.31) v2(77.96,11.55) v2(77.96,10.78) v2(78.63,15.36) v2(78.63,14.59) v2(78.63,13.83) v2(78.63,13.07) v2(78.63,12.31) v2(78.63,11.55) v2(78.63,10.78) v2(79.39,15.36) v2(79.39,14.59) v2(79.39,13.83) v2(79.39,13.07) v2(79.39,12.31) v2(79.39,11.55) v2(79.39,10.78) v2(80.05,15.36) v2(80.05,14.59) v2(80.05,13.83) v2(80.05,13.07) v2(80.05,12.31) v2(80.05,11.55) v2(80.05,10.78)
N01977: length 2.4
  BOTTOM w0.188: C61.2 75.14,15.2 74.41,14.46 U5.6
N02113: length 1.6
  TOP w0.254: U4.7 86.98,7.01 87.48,7.51 C41.1
N02139: length 6.3
  TOP w0.254: R22.2 R16.1 70.63,12.75 v2(70.89,12.49)
  BOTTOM w0.254: v2(70.89,12.49) 70.89,12.86 70.64,13.12 R58.1 70.1,13.76 70.35,14.01 U5.2
N02147: length 8.1
  TOP w0.254: C18.1 R29.2 71.79,16.38 71.61,16.2 71.35,16.2 71.1,16.45 R15.1 70.63,17.05 v2(70.45,17.23)
  BOTTOM w0.254: U5.3 71.39,14.46 70.9,14.95 R60.1 R59.1 v2(70.45,17.23)
N02197: length 3.7
  BOTTOM w0.188: U5.5 73.96,14.91 74.46,15.4 74.46,17 74.71,17.26 R54.2
N02205: length 2.9
  BOTTOM w0.188: R57.2 R56.2 U5.4
N02555: length 5.7
  BOTTOM w0.188: R59.2 69.01,20.15 69.79,20.94 Q14.3
N15498: length 8.1
  TOP w0.188: C12.2 SW2.2 SW2.1 ; C12.2 R17.2 ; C12.2 R20.2
N16041498: length 7.3
  TOP w0.508: TP8.1 102.01,10.41 ; TP8.1 101.1,11.32 ; TP8.1 101.1,9.49 ; TP8.1 100.19,10.41
  BOTTOM w0.508: 101.1,9.49 TP8.1 ; TP8.1 101.1,11.32 ; TP8.1 100.19,10.41 ; TP8.1 102.01,10.41
  vias: v2(102.06,8.52) v2(102.06,7.96) v2(102.07,5.1) v2(102.07,4.54) v2(102.63,5.07) v2(102.7,8.52) v2(102.7,7.96) v2(102.71,4.54) v2(106.05,7.4) v2(106.05,6.84) v2(106.05,5.4) v2(106.05,4.84)
N16043536: length 12.5
  TOP w0.508: 103.14,1.68 J10.SH1 ; J10.SH1 105.65,1.68 ; J10.SH1 104.39,0.93 ; 105.65,10.32 J10.SH2 104.39,11.07 ; 107.25,1.38 J10.SH3 109.75,2.13 ; 107.25,10.62 J10.SH4 ; J10.SH4 109.75,11.37 ; J10.SH4 109.75,9.87
N16124091: length 3.5
  TOP w0.254: U4.9 v2(85.98,7.17)
  BOTTOM w0.254: R53.1 87.86,6.82 87.52,7.17 v2(85.98,7.17)
N16800802: length 1.4
  TOP w0.188: R18.2 69.53,43.31 69.63,43.21 LED3.A
N16801019: length 1.5
  TOP w0.188: R21.2 71.08,41.81 71.13,41.86 LED3.K
N16919447: length 9
  TOP w0.188: U3.46 79.61,35.42 82.36,32.68 C31.2 R41.2 84.88,32.2 85.08,32 TP6.1
N17059836: length 10.1
  TOP w0.188: U3.14 80.01,45.58 80.45,46.02 82.69,46.02 82.88,46.21 82.88,46.81 C34.1 82.44,46.83 82.26,47.01 82.26,49.19 82.68,49.61 R40.2
N17062103: length 5.4
  TOP w0.188: U3.45 79.21,35.34 81.21,33.34 C29.2
N17063422: length 8.7
  TOP w0.188: U3.15 79.61,45.7 80.74,46.83 C30.1 81.71,46.83 81.92,47.04 81.92,49.05 81.36,49.61 R39.2
N17316342: length 1.8
  TOP w0.188: R42.2 84.97,48.45 85.1,48.58 C39.1
N17354900: length 8.2
  TOP w0.381: D19.K D18.K 68.99,49.64 68.6,49.24 TP5.1 67.15,48.6 v1(67.15,48.6)
  BOTTOM w0.381: R32.2 v1(67.15,48.6)
N17368419:
  vias: v1(14.23,44.79) v1(18.89,44.7) v1(20.8,44.7)
N17368440: length 4.3
  TOP w0.61: R6.1 18.64,47.53 18.4,47.29 Q2.3 19.05,45.94 Q3.1
N17368442: length 4.7
  TOP w0.61: R5.1 15.79,46.08 16.4,46.69 Q2.1 16.4,47.35 15.79,47.96 D3.K
N17400441: length 1.4
  BOTTOM w0.188: R56.1 C62.1
N17416139: length 2.9
  TOP w0.14: R48.1 97.25,66.55 97.39,66.41 SP3.2
  vias: v4(90.94,67.77) v4(90.94,66.5) v4(90.94,65.23) v4(90.94,63.96) v4(92.21,67.77) v4(92.21,66.5) v4(92.21,65.23) v4(92.21,63.96) v4(93.48,67.77) v4(93.48,66.5) v4(93.48,65.23) v4(93.48,63.96) v4(94.75,67.77) v4(94.75,66.5) v4(94.75,65.23) v4(94.75,63.96)
N17416161: length 2.2
  BOTTOM w0.188: v1(87.7,66.02) D7.1 87.7,65.13 88.07,64.76 R43.1
N17416246: length 2.9
  TOP w0.14: R45.1 91.08,29.67 90.92,29.51 SP1.1
  vias: v2(90.61,36.38) v2(90.61,35.74) v2(90.61,35.11) v2(90.61,34.47) v2(91.24,36.38) v2(91.24,35.74) v2(91.24,35.11) v2(91.24,34.47) v2(91.88,36.38) v2(91.88,35.74) v2(91.88,35.11) v2(91.88,34.47) v2(92.49,36.32) v2(92.51,35.74) v2(92.51,35.11) v2(92.51,34.47)
N17416442: length 20
  TOP w0.508: Q5.4 v1(86.62,69.11) ; Q9.4 v1(89.1,63.2)
  BOTTOM w0.508: v1(89.1,63.2) Q9.4 D7.2 89.1,68.56 88.55,69.11 v1(86.62,69.11) 78.23,69.11 77.72,68.61 Q4.3
N17416846: length 4.3
  BOTTOM w0.188: R33.1 R36.1 ; R36.1 R38.1 ; R36.1 Q4.1
N17479997: length 1.5
  TOP w0.508: D6.K R14.1
N17481687: length 1.3
  TOP w0.188: LED4.A R28.2
N17511481: length 6.5
  TOP w0.254: v2(85.48,7.52) 85.48,7.43 85.48,7.43 U4.10
  BOTTOM w0.254: R52.2 90.05,7.49 89.71,7.83 85.79,7.83 v2(85.48,7.52)
N17631535: length 4.6
  BOTTOM w0.188: TP11.1 64.28,40.99 63.9,41.37 R83.2 R84.2 R85.2
N17633702: length 28.3
  TOP w0.203: R81.1 v1(68.66,35.66) ; C89.1 R90.1 v1(77.24,56.73)
  PWR/SIG w0.381: v1(68.66,35.66) 69.39,36.39 69.39,44.93 74.1,49.65 74.1,53.59 v1(77.24,56.73)
N17633741: length 5.6
  TOP w0.381: R86.2 78.51,69.05 J13.2
N17633795: length 5.7
  TOP w0.381: R87.2 75.72,68.8 J13.3
N17633797: length 5.8
  TOP w0.381: J13.4 72.92,68.54 R88.2
N17633812: length 5.9
  TOP w0.381: R89.2 70.13,68.29 J13.5
N17661501: length 2.9
  TOP w0.254: R44.2 86.88,8.51 86.48,8.11 U4.8
N17663299: length 6
  TOP w0.254: v2(91.99,1.63) Q6.4
  BOTTOM w0.254: v2(91.99,1.63) 91.99,4.99 91.61,5.37 R52.1
N19965120: length 1.9
  TOP w0.188: C1.1 11.05,34.72 U1.31
N19965125: length 2.4
  TOP w0.188: U1.53 20.64,33.92 v5(21.47,34.75)
  BOTTOM w0.188: C69.1 v5(21.47,34.75)
N19965127: length 2.3
  TOP w0.188: U1.42 15.73,32.02 15.37,31.66 15.37,31.07 C5.1
N19965162: length 6.9
  TOP w0.14: U1.22 11.67,38.32 arc(11.63,38.31) 11.6,38.29 arc(11.59,38.28) 11.58,38.28 11.28,38.28 arc(10.84,38.45) 10.65,38.88 arc(10.65,38.89) 10.65,38.9 10.65,39.03 arc(10.65,39.05) 10.65,39.07 arc(10.52,39.55) 10.24,39.96 9.33,40.86 9.33,40.87 arc(9.23,41.02) 9.2,41.19 9.2,41.46 arc(9.21,41.54) 9.26,41.6 9.5,41.84 v1(9.52,41.84)
  BOTTOM w0.14: v1(9.52,41.84) 9.52,41.84 9.34,41.66 arc(9.24,41.51) 9.2,41.34 9.2,41.02 arc(9.24,40.93) 9.33,40.89 R67.2
N19965164: length 7.4
  TOP w0.14: v1(8.6,41.84) 8.87,41.57 arc(8.9,41.53) 8.91,41.48 8.91,41.2 arc(8.96,40.9) 9.13,40.66 10.03,39.75 arc(10.26,39.43) 10.36,39.04 arc(10.36,39.04) 10.36,39.03 10.36,38.9 arc(10.63,38.24) 11.29,37.97 11.53,37.97 arc(11.57,37.97) 11.6,37.94 arc(11.63,37.92) 11.67,37.92 U1.23
  BOTTOM w0.14: R68.2 8.78,40.89 arc(8.87,40.93) 8.91,41.02 8.91,41.35 arc(8.88,41.52) 8.79,41.65 v1(8.6,41.84)
N19965683: length 2
  TOP w0.381: LED2.A v5(28.55,48.89)
  BOTTOM w0.381: R61.2 v5(28.55,48.89)
N19965698: length 3.2
  TOP w0.188: v5(9.02,27.6) LED1.A
  BOTTOM w0.188: R66.2 9.9,27.95 9.55,27.6 v5(9.02,27.6)

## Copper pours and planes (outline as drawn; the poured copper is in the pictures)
5V on TOP: 77.04,53.12 77.04,54.76 77.16,54.87 79.96,54.87 80.03,54.8 80.03,53.15 79.93,53.05 77.12,53.05
GND on TOP: 99.96,55.13 99.74,55.36 99.74,59.43 99.86,59.55 101.89,59.55 102.08,59.74 102.08,61.39 102.26,61.57 110.77,61.57 110.99,61.35 110.99,55.3 110.83,55.13
GND on TOP: 70.39,0.54 68.98,1.13 68.4,2.55 68.4,22.36 68.67,22.63 79.26,22.63 89.63,12.27 89.63,7.83 88.8,7 88.8,4.39 88.61,4.2 85.01,4.2 84.93,4.29 84.93,15.8 81.52,19.2 72.49,19.2 72.14,18.85 72.14,14.12 72.01,13.99 71.16,13.99 71.16,14.7 70.11,14.7 70.11,13.91 70.15,13.91 70.1,13.87 70.1,12.72 69.34,11.96 69.34,8.64 69.67,8.31 72.43,8.31 72.71,8.6 72.71,10.89 73.03,11.2 73.03,13.62 73.1,13.7 76.95,13.7 77.3,13.34 77.3,10.17 77.55,9.92 80.9,9.92 81.23,9.58 81.23,3.01 81.76,2.48 84.13,2.48 84.25,2.35 84.25,0.69 84.1,0.54 ; 4 cut-outs
GND on TOP: 68.43,70.94 69.01,72.34 70.41,72.92 108.98,72.92 110.38,72.34 110.96,70.94 110.96,2.54 110.38,1.14 108.98,0.56 81.15,0.56 81.05,0.66 81.05,2.23 81.2,2.37 83.49,2.37 84.77,1.09 89.86,1.09 90.01,1.24 90.01,2.14 91.8,2.14 91.8,2.61 90.01,2.61 90.01,12.59 79.52,23.08 69.37,23.08 68.29,24.16 65.31,24.16 65.1,23.95 2.54,23.95 1.14,24.53 0.56,25.93 0.56,47.55 1.14,48.95 2.54,49.53 65.33,49.53 67.52,50.44 68.43,52.63 68.43,59.91 68.57,59.91 68.57,59.63 69.23,59.63 69.23,60.64 68.9,60.64 68.9,62.16 68.43,62.16 ; 126 cut-outs
GND on BOTTOM: 110.8,2.16 110.83,2.17 110.91,2.22 110.93,2.24 110.94,2.26 110.96,2.4 110.96,2.54 110.96,9.73 110.96,9.75 110.89,9.81 110.89,11.18 110.64,11.43 103.47,11.43 102.84,12.05 98.17,12.05 97.82,11.7 97.82,6.61 98.15,6.27 100.8,6.27 101.05,6.02 101.05,1.31 101.05,0.76 100.86,0.56 100.86,0.56 81.15,0.56 81.05,0.66 81.05,2.22 81.2,2.37 83.49,2.37 83.99,1.87 89.27,1.87 90.01,2.61 90.01,12.59 79.52,23.08 68.57,23.08 67.7,23.95 2.54,23.95 1.14,24.53 0.56,25.93 0.56,47.55 1.14,48.95 2.54,49.53 65.33,49.53 67.52,50.44 68.43,52.63 68.43,70.94 69.01,72.34 70.41,72.92 108.98,72.92 110.38,72.34 110.96,70.94 110.96,2.54 110.38,1.14 108.98,0.56 101.64,0.56 101.71,0.62 101.71,0.66 101.72,0.65 109.1,0.65 110.65,2.2 110.72,2.18 110.78,2.16 ; 52 cut-outs
GND on BOTTOM: 79.26,22.63 68.67,22.63 68.4,22.36 68.4,2.55 68.98,1.13 70.39,0.54 88.49,0.54 88.8,0.85 88.8,7 89.63,7.83 89.63,12.27 ; 9 cut-outs
GND on BOTTOM, GND, PWR/SIG: 99.96,55.13 99.74,55.36 99.74,61.36 99.95,61.57 110.77,61.57 110.99,61.35 110.99,55.3 110.83,55.13
GND on GND: 68.43,70.94 69.01,72.34 70.41,72.92 108.98,72.92 110.38,72.34 110.96,70.94 110.96,2.54 110.38,1.14 108.98,0.56 81.15,0.56 81.05,0.66 81.05,2.22 81.2,2.37 83.49,2.37 83.99,1.87 89.26,1.87 90.01,2.62 90.01,12.59 79.52,23.08 69.37,23.08 68.5,23.95 2.54,23.95 1.14,24.53 0.56,25.93 0.56,47.55 1.14,48.95 2.54,49.53 65.33,49.53 67.52,50.44 68.43,52.63 ; 4 cut-outs
GND on GND: 79.26,22.63 68.67,22.63 68.4,22.36 68.4,2.55 68.98,1.13 70.39,0.54 88.49,0.54 88.8,0.85 88.8,7 89.63,7.83 89.63,12.27
GND on PWR/SIG: 79.26,22.63 68.67,22.63 68.4,22.36 68.4,2.55 69,1.15 70.39,0.54 88.7,0.54 88.8,0.63 88.8,7 89.63,7.83 89.63,12.27
GND on PWR/SIG: 81.15,0.56 81.05,0.66 81.05,2.22 81.2,2.37 83.49,2.37 83.99,1.87 89.25,1.87 89.74,2.36 90.01,2.36 90.01,12.59 79.52,23.08 69.37,23.08 68.29,24.16 65.31,24.16 65.1,23.95 2.54,23.95 1.14,24.53 0.56,25.93 0.56,47.55 1.14,48.95 2.54,49.53 65.33,49.53 67.52,50.44 68.43,52.63 68.43,70.94 69.01,72.34 70.41,72.92 108.98,72.92 110.38,72.34 110.96,70.94 110.96,2.54 110.38,1.14 108.98,0.56 ; 43 cut-outs
GND_EARTH1 on TOP: 5.82,28.44 6.33,28.95 6.33,33.09 3.78,35.64 3.78,38.74 5.14,40.1 6.13,41.09 6.13,43.91 5.45,44.59 0.75,44.59 0.56,44.4 0.56,28.83 0.95,28.44
GND_EARTH1 on BOTTOM: 0.75,44.59 4.35,44.59 6,42.94 6,40.96 4.35,39.31 4.35,35.07 6.7,32.72 7.78,32.72 8.12,32.38 8.12,29.49 7.07,28.44 0.95,28.44 0.52,28.88 0.52,44.36 ; 1 cut-out
VBUS_TYPE-C on TOP (solid shape): 97.07,12.93 92.62,12.93 92.62,17.34 97.07,17.34
VBUS_TYPE-C on TOP (solid shape): 89.71,4.33 90.02,4.33 90.02,4.98 90.36,4.98 90.36,4.33 90.67,4.33 90.67,4.98 91.01,4.98 91.01,4.33 91.32,4.33 91.32,4.98 91.66,4.98 91.66,2.62 89.37,2.62 89.37,4.98 89.71,4.98
VBUS_TYPE-C on TOP: 89.37,2.78 89.37,7.05 90.02,7.71 90.02,17.07 90.42,17.47 97.06,17.47 97.1,17.43 97.1,8.33 96.92,8.15 93.1,8.15 92.68,7.74 92.68,3.71 91.6,2.62 89.52,2.62
VBUS_TYPE-C on BOTTOM, GND, PWR/SIG: 97.03,13.04 97.03,17.28 96.84,17.46 93.77,17.46 93.6,17.28 93.6,13.02 93.83,12.8 96.79,12.8
VBUS_TYPE-C on BOTTOM, GND, PWR/SIG: 89.45,4.21 91.55,4.21 91.65,4.12 91.65,2.72 91.53,2.61 89.47,2.61 89.36,2.71 89.36,4.12
VCC_IN on TOP: 43.29,44.78 43.29,42.71 43.4,42.6 46.1,42.6 46.22,42.72 46.22,44.75 46.14,44.82 43.33,44.82
B1_VDDD on TOP: 76.68,42.44 76.68,44.12 76.43,44.37 73.76,44.37 73.66,44.47 73.66,48.23 73.76,48.33 74.4,48.33 74.5,48.23 74.5,45.44 75.21,44.73 76.66,44.73 76.94,44.45 76.94,42.44 76.86,42.37 76.76,42.37
BB_IN on TOP (solid shape): 107.81,12.93 103.35,12.93 103.35,17.34 107.81,17.34
BB_IN on TOP: 103.35,12.89 103.35,18.23 103.14,18.45 90.14,18.45 89.21,19.38 89.21,28.7 89.38,28.87 92.78,28.87 92.87,28.78 92.87,23.38 93.2,23.06 108.43,23.06 108.72,22.77 108.72,13 108.53,12.81 103.43,12.81
BB_IN on BOTTOM, GND, PWR/SIG: 106.86,13.03 106.86,17.27 106.68,17.45 103.61,17.45 103.43,17.28 103.43,13.01 103.66,12.79 106.62,12.79
HG2 on TOP: 93.13,45.49 93.13,44.64 93.28,44.49 94.08,44.49 94.24,44.64 94.24,45.42 94.09,45.57 93.21,45.57
KP_VBUS_IN on TOP: 9.95,45.64 13.15,45.64 13.4,45.89 13.4,46.89 13.3,46.99 10.15,46.99 9.7,47.44 9.15,47.44 9.15,47.45 7.95,47.45 7.85,47.34 7.85,46.74 8,46.59 9,46.59
KP_VBUS_IN on BOTTOM: 14.8,46.6 14.8,48.78 14.53,49.05 11.34,49.05 9.24,46.96 9.24,46.02 9.44,45.82 11.06,45.82 11.73,46.49 14.69,46.49
KP_VBUS_IN on PWR/SIG: 3.75,36.82 3.75,34.49 4.37,33.87 7.48,33.87 7.76,34.15 7.76,34.62 7.25,35.13 7.25,38.65 7.79,39.19 7.79,39.52 7.65,39.66 6.59,39.66
KP_VBUS_IN on PWR/SIG: 7.61,45.72 7.61,48.34 8.58,49.31 20.68,49.31 21.1,48.89 21.1,47.06 20.87,46.83 12.66,46.83 10.87,45.04 8.29,45.04
KP_VBUS_P on TOP: 21.35,45.24 21.35,46.14 21.8,46.59 23.2,46.59 23.3,46.49 23.3,44.59 23,44.29 22.3,44.29
KP_VBUS_P on BOTTOM: 13.85,45.22 13.51,45.57 12.72,45.57 11.9,44.74 11.9,44.1 11.81,44.01 10.73,44.01 10.66,44.07 10.66,45.05 11.85,46.24 20.29,46.24 20.6,46.55 23.05,46.55 23.7,45.89 23.7,44.63 23.35,44.29 22.23,44.29 21.29,45.22
KP_VBUS_P on PWR/SIG: 22,47.49 22,44.69 22.4,44.29 25.1,44.29 27.2,46.39 27.6,46.39 28.35,45.64 28.75,45.64 29.1,45.99 29.1,47.79 28.1,48.79 23.3,48.79
LG1 on TOP: 97.69,36.21 99.05,36.21 99.13,36.3 99.13,37.03 99.06,37.09 97.67,37.09 97.6,37.02 97.6,36.31
LG2 on TOP: 97.69,44.48 99.05,44.48 99.13,44.56 99.13,45.29 99.06,45.35 97.67,45.35 97.6,45.28 97.6,44.57
P5LP_VDD on PWR/SIG: 10.79,35.31 11.44,34.66 11.44,30.87 11.82,30.5 19.32,30.5 21.77,32.95 21.77,34.94 21.03,35.68 21.03,36.33 21.29,36.59 22.2,36.59 23.6,37.99 23.6,40.69 23,41.29 20.47,41.29 17.77,43.99 12.43,43.99 11.7,43.26 11.7,40.15 12.06,39.79 12.06,38.69 11.05,37.68 10.58,37.68 10.01,37.1 9.54,37.1 8.01,35.56 8.01,33.43 7.3,32.72 7.3,25.24 7.7,24.84 10.06,24.84 10.27,25.05 10.27,34.12 10.24,34.15 10.24,36.04 10.39,36.19 10.52,36.19 10.79,35.92
SW_1 on TOP, BOTTOM, GND: 93.22,35.92 94.13,35.92 94.78,36.57 97.14,36.57 97.21,36.5 97.21,34.34 97.14,34.28 93.2,34.28 93.18,34.29 93.18,35.88
SW_1 on TOP, GND: 107.9,33.72 101.7,33.72 101.43,33.98 101.43,36.88 101.74,37.19 107.9,37.19 108.18,36.9 108.18,34
SW_1 on BOTTOM: 107.9,33.72 101.7,33.72 101.43,33.98 101.43,36.88 101.74,37.19 107.9,37.19 108.18,36.9 108.18,34
SW_1 on PWR/SIG: 107.9,37.19 101.74,37.19 101.43,36.88 101.43,33.99 101.24,33.79 96.66,33.79 96.47,33.98 96.47,36.44 96.35,36.56 94.9,36.56 94.76,36.42 94.76,36.06 94.64,35.93 93.22,35.93 93.15,35.86 93.15,32.14 93.47,31.82 107.71,31.82 108.18,32.3 108.18,36.9
SW_2 on TOP, BOTTOM, GND: 93.22,44.18 94.13,44.18 94.78,44.83 97.14,44.83 97.21,44.76 97.21,42.61 97.14,42.54 93.2,42.54 93.18,42.55 93.18,44.14
SW_2 on TOP, BOTTOM, GND: 107.9,42.66 101.7,42.66 101.43,42.92 101.43,45.82 101.74,46.13 107.92,46.13 108.18,45.87 108.18,42.94
SW_2 on PWR/SIG: 107.9,42.66 101.7,42.66 101.43,42.92 101.43,45.81 101.26,45.99 96.72,45.99 96.47,45.74 96.47,42.64 96.37,42.54 93.3,42.54 93.19,42.65 93.19,44.1 93.28,44.18 94.75,44.18 94.84,44.28 94.84,47.71 95.15,48.02 107.95,48.02 108.18,47.79 108.18,42.94
VOUT on TOP: 92.79,39.86 92.87,39.94 92.87,53.3 85.32,60.85 85.32,68.11 85.23,68.21 80.39,68.21 80.32,68.14 80.32,59.47 89.2,50.59 89.2,39.97 89.31,39.86
VOUT on BOTTOM: 80.4,61.56 86.25,61.56 86.38,61.69 86.38,62.96 85.32,64.02 85.32,68.12 85.23,68.21 80.39,68.21 80.32,68.14 80.32,61.64
VOUT on BOTTOM: 85.62,41.59 85.62,39.75 85.54,39.67 84.61,39.67 84.52,39.77 84.52,41.57 84.61,41.67 85.54,41.67
VOUT on BOTTOM, GND: 90.52,44.85 92.62,44.85 92.71,44.76 92.71,42.62 92.61,42.52 90.49,42.52 90.39,42.63 90.39,44.72
VOUT on GND, PWR/SIG: 80.81,63.57 84.96,63.57 85.18,63.79 85.18,67.92 84.95,68.15 80.81,68.15 80.59,67.94 80.59,63.79
VOUT on PWR/SIG: 90.52,44.85 92.62,44.85 92.71,44.76 92.71,43.26 92.61,43.16 90.52,43.16 90.39,43.29 90.39,44.72
VOUT_BUCK on TOP: 81.81,3.25 81.98,3.08 86.04,3.08 86.1,3.14 86.1,3.8 86.07,3.83 84.71,3.83 84.51,4.04 84.51,15.7 81.42,18.78 73.02,18.78 72.91,18.68 72.91,16.61 73.02,16.51 80.73,16.51 81.81,15.42
VOUT_BUCK on BOTTOM: 81.81,15.7 81.81,3.25 81.98,3.08 84.34,3.08 84.51,3.24 84.51,15.7 84.38,15.83 81.94,15.83
VOUT_BUCK on GND, PWR/SIG: 81.81,15.7 81.81,10.48 81.98,10.31 84.35,10.31 84.51,10.47 84.51,15.7 84.37,15.83 81.95,15.83
VOUT_DC on TOP: 98.03,64.46 98.03,68.51 98.22,68.7 108.44,68.7 108.69,68.45 108.69,62.61 108.4,62.33 102.28,62.33 102.09,62.52 102.09,64.06 101.85,64.3 98.19,64.3
VOUT_DC on BOTTOM, GND, PWR/SIG: 100.06,68.7 108.44,68.7 108.69,68.45 108.69,62.61 108.4,62.33 99.86,62.33 99.74,62.45 99.74,68.38
VOUT_U2 on TOP (solid shape): 91.01,1.18 90.67,1.18 90.67,1.63 90.36,1.63 90.36,1.18 90.02,1.18 90.02,1.63 89.71,1.63 89.71,1.18 89.37,1.18 89.37,2.08 91.01,2.08
VOUT_U2 on TOP: 86.35,3.79 86.35,1.18 86.4,1.13 90.97,1.13 91.01,1.16 91.01,2.06 90.98,2.08 89.36,2.08 88.98,2.47 87.76,2.47 87.1,3.13 87.1,3.75 87.02,3.83 86.4,3.83
VS_IN on TOP: 69.85,8.66 72.01,8.66 72.14,8.79 72.14,10.95 72.26,11.07 72.26,13.61 72.14,13.74 71.5,13.74 71.37,13.61 71.37,12.47 70.93,12.03 69.91,12.03 69.6,11.71 69.6,8.91
VS_IN on BOTTOM: 72.26,13.58 72.26,3.44 72.07,3.26 69.76,3.26 69.54,3.47 69.54,11.94 69.62,12.02 71.2,12.02 71.29,12.11 71.29,13.64 71.33,13.68 72.15,13.68
VS_IN on GND, PWR/SIG: 69.85,8.66 72.01,8.66 72.14,8.79 72.14,10.95 72.26,11.07 72.26,13.61 72.14,13.74 71.5,13.74 71.37,13.61 71.37,12.47 69.6,10.69 69.6,8.91
N01675 on TOP: 80.09,15.83 80.26,15.66 80.26,10.47 80.11,10.31 77.78,10.31 77.67,10.42 77.67,13.73 77.41,13.99 73.09,13.99 72.82,13.72 72.82,12.11 72.77,12.06 72.51,12.06 72.46,12.11 72.46,15.61 72.68,15.83
N01675 on BOTTOM: 74.47,14.16 74.9,14.6 77.54,14.6 77.67,14.73 77.67,15.62 77.88,15.83 80.09,15.83 80.26,15.66 80.26,10.47 80.11,10.31 77.78,10.31 77.67,10.42 77.67,13.23 77.48,13.42 74.89,13.42 74.45,13.86 72.91,13.86 72.81,13.77 72.81,12.01 72.78,11.98 72.49,11.98 72.48,11.99 72.48,13.87 72.77,14.16
N01675 on GND: 77.67,15.62 77.89,15.83 80.09,15.83 80.26,15.66 80.26,10.47 80.1,10.31 77.78,10.31 77.67,10.42
N01675 on PWR/SIG: 77.67,15.62 77.89,15.83 80.09,15.83 80.26,15.66 80.26,10.47 80.1,10.31 77.78,10.31 77.67,10.42
N16041498 on TOP: 98.16,6.76 98.16,11.5 98.46,11.8 102.7,11.8 103,11.5 103,7.82 103.16,7.65 104.68,7.65 104.93,7.4 105.74,7.4 106.08,7.75 107,7.75 107.12,7.62 107.12,4.74 106.98,4.6 105,4.6 104.74,4.35 102,4.35 101.9,4.45 101.9,6.56 101.81,6.65 98.29,6.65 98.28,6.64 ; 6 cut-outs
N16041498 on BOTTOM: 98.16,6.76 98.16,11.5 98.37,11.71 102.78,11.71 103,11.5 103,9.69 103.14,9.54 109.91,9.54 110.3,9.15 110.3,2.73 110.05,2.49 101.56,2.49 101.37,2.68 101.37,6.47 101.18,6.65 98.27,6.65 ; 3 cut-outs
N16043536 on TOP: 97.87,2.08 97.74,1.94 97.74,0.59 97.81,0.52 109.13,0.52 110.43,1.13 111.01,2.44 111.01,11.63 110.84,11.8 103.53,11.8 103.25,11.52 103.25,9.91 103.42,9.75 108.3,9.75 108.65,9.41 108.65,2.59 108.3,2.24 103.66,2.24 103.49,2.08
N17354936 on BOTTOM: 71.95,53.56 71.95,52.42 71.56,52.02 69.05,52.02 68.9,51.87 68.9,49.87 69.05,49.72 70.88,49.72 72.3,51.14 72.3,53.58 72.28,53.6 72,53.6
N17354948 on BOTTOM: 74.83,53.6 74.59,53.6 74.55,53.57 74.55,51.3 74.63,51.22 77.78,51.22 77.91,51.35 77.91,52.44 77.82,52.52 74.97,52.52 74.9,52.59 74.9,53.54
N17368419 on TOP: 12.72,44.45 12.72,43.79 12.85,43.66 13.88,43.66 14.37,44.15 20.86,44.15 21.1,44.39 21.1,44.79 20.6,45.29 19.37,45.29 19.22,45.14 17.44,45.14 17.17,45.41 14.48,45.41 13.68,44.61 12.88,44.61
N17368419 on PWR/SIG: 13.87,44.73 13.87,45.46 14.3,45.89 21.1,45.89 21.3,45.69 21.3,44.69 20.9,44.29 18.7,44.29 18.5,44.49 14.11,44.49
N17416139 on TOP: 90.39,68.35 90.39,63.66 90.53,63.52 95.57,63.52 97.13,65.09 97.13,68.41 96.9,68.64 90.68,68.64
N17416139 on BOTTOM, GND, PWR/SIG: 90.77,63.57 94.92,63.57 95.15,63.79 95.15,67.92 94.91,68.16 90.77,68.16 90.55,67.94 90.55,63.79
N17416161 on TOP: 87.27,63.58 85.99,63.58 85.97,63.6 85.97,66.82 86.03,66.87 87.18,66.87 88.55,68.24 89.8,68.24 89.88,68.16 89.88,64.78 89.72,64.62 88.31,64.62
N17416246 on TOP: 92.78,29.77 92.87,29.87 92.87,39.16 92.79,39.24 89.33,39.24 89.21,39.12 89.21,29.95 89.38,29.77
N17416246 on BOTTOM, GND, PWR/SIG: 90.5,36.53 92.65,36.53 92.71,36.46 92.71,34.37 92.61,34.27 90.5,34.27 90.39,34.38 90.39,36.42
N17416547 on TOP: 100.2,63.67 101.58,63.67 101.7,63.55 101.7,60.31 101.59,60.2 100.18,60.2 100.12,60.26 100.12,63.58
N17422796 on TOP: 98.41,16.02 99.58,16.02 100.85,17.29 102.03,17.29 102.08,17.24 102.08,14.3 102.04,14.25 100.84,14.25 99.57,12.98 98.37,12.98 98.35,13 98.35,15.96
N17618145 on BOTTOM: 87.13,59.73 87.13,62.76 87.2,62.83 87.92,62.83 88.53,62.22 88.53,59.74 88.46,59.67 87.19,59.67

Small or netless copper shapes (teardrops, artwork), in the pictures only: 1 on TOP

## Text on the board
BOTTOM: BOTTOM SIDE
Ref Des/Assembly Bottom: ASSEMBLY BOTTOM
Board Geometry/Soldermask Bottom: SOLDERMASK BOTTOM
Ref Des/Silkscreen Bottom: QRCODE | EN.H | SOURCE.BUCK | 1 | 2 | J3 | J4 | J6 | J7 | 6 | 3 | KP.VBUS | I2C.SCL | I2C.SDA | UART.RX | UART.TX | SWDCLK | RESET | SWDIO | VDDD | GND | B1.VDD | BARCODE | DM.GPIO1 | DP.GPIO0 | SOURCE.FAULT.FLAG | UART2.TX/AIN2 | SWD.DAT | SWD.CLK | UART2.RX/AIN1 | SOURCE.OUTPUT.V.SELECT | P1.7 | LED | USER.STATUS | I2C0.SDA | I2C0.SCL | B1.VOUT.DC | CC2 | P1.4/AIN3 | LOAD.SWITCH | .EN.H | CC1 | P1.3/AIN4 | USER.SWITCH | 5V | SILKSCREEN BOTTOM
TOP: TOP SIDE
Ref Des/Assembly Top: 10 | 2 | 9 | ASSEMBLY TOP
Board Geometry/Soldermask Top: SOLDERMASK TOP
Ref Des/Silkscreen Top: KITPROG3 | STATUS. | USB | A1 | CY8C5868LTI.LP039 | MODE | KP.POWER. | 12 | 6 | USER.SWITCH | POWER | CYPM1116-48LQXI | 2PIN.OUTPUT | 5V-22V | A | KP.VBUS.P | RESET.SWITCH | 2PIN.INPUT | 9V-22V | 600-60657-01 | USB-PD | EVAL_PMG1_B1_DRP KIT REV02 | 21V | SILKSCREEN TOP
GND: GND-2
PWR/SIG: PWR-3
PASTEMASK_TOP: SOLDERPASTE TOP
PAGE_OUTLINE: SOLDERPASTE BOTTOM
COMPVAL_TYPE_TOP: GOLDMASK TOP
TOLERANCE_TOP: GOLDMASK BOTTOM
User.17: PROJECT: | DRAWN BY: | LAYER: | DWG NO: | REV: | DATE: | 1 | J4 | J8 | LED2 | R5 | R4 | C12 | R13 | C20 | C10 | R10 | C6 | C14 | C18 | LED1 | SW3 | R34 | R33 | R31 | R32 | SW1 | U6 | J1 | J2 | LED4 | LED3 | SW2 | R48 | R45 | R46 | R49 | R47 | C37 | L4 | J9 | JMP1 | C8 | C9 | R19 | C13 | U2 | C19 | R12 | R11 | J7 | J5 | U1 | J3 | JMP2 | J6 | R21 | C56 | C34 | U5 | SAN JOSE, CA 95134 | (408) 943-2600 | ASSEMBLY TOP | PSoC 64S1 SECUREBOOT PROT0TYPING KIT | PRAO | 610-60545-01 | 04 | 09/20/19
User.19: j | i | h | g | f | e | d | c | b | a | 1 | 30
User.25: 10.FOLLOW VIA FILLING METHOD AS PER BELOW NOTES: | A. COMMON FOR ALL VIAS: | C. FILL ALL THRU VIAS USING NON-CONDUCTIVE EPOXY AND OVERPLATE WITH COPPER, .005 [.0002] | B. SEE LAYER STACK-UP FOR IMPEDANCE REQUIREMENTS. | INTENTIONAL NET SHORT | 2. VOUT_DC & IOUT_CSN | 1. N17416139 & IOUT_CSP | 3. BB_IN & IIN_CSP | 4. N17416246 & IIN_CSN | II. FILL ALL VIA HOLES 7.87 MILL, 8 MILL, 10 MILL, 15 MILL WITH NONCONDUCTIVE EPOXY | MINIMUM THICKNESS. DIMPLE DEPTH IN BGA PADS SHALL BE .025 [.001] MAXIMUM. THE PRESENCE | OF WRAP PLATING SHALL BE VISUALLY EVIDENT IN ALL QUALITY CONFORMANCE MICROSECTIONS; NO | MINIMUM MEASUREMENT REQUIRED. | I. VIA WALL THICKNESS MIN 35um COPPER
User.26: LAYER | DESCRIPTION | L01 - TOP | L02 - PLANE | L03 - PWR/SIG | L04 - BOTTOM | (2 OZ) | COPPER | 0.070 mm | FINISH | WT | IMP | OHMS | 50E | SE | -- | 0.1498 mm | 0.1879 mm | ----- | TRACE | WIDTH | --- | L02 | L03 | DIFF | 90E | 0.1397/0.1524 mm | 0.1143/0.1778 mm | WIDTH/SPACE | ---- | 1.6 mm | +/- 10% | REF | STACK-UP
User.29: 14/12/23
User.30: 2
User.45: FIGURE | FINISHED_SIZE | 7.87 | 8.0 | 10.0 | 15.0 | 40.0 | 40.157 | 40.161 | 43.307 | 47.244 | 51.0 | 23.618 | 62.988x23.618 | 62.992x23.622 | 74.799x23.618 | 82.677x23.622 | 33.461x23.618 | 60.0x30.0 | 240.0x30.0 | DRILL CHART: TOP to BOTTOM | ALL UNITS ARE IN MILS | TOLERANCE_DRILL | +1.969/-1.969 | +3.0/-3.0 | +2.988/-2.988 | +2.0/-2.0 | PLATED | NON-PLATED | QTY | 62 | 335 | 122 | 348 | 11 | 24 | 22 | 5 | 2 | 1 | 4 | 951 | TOTAL HOLES:
